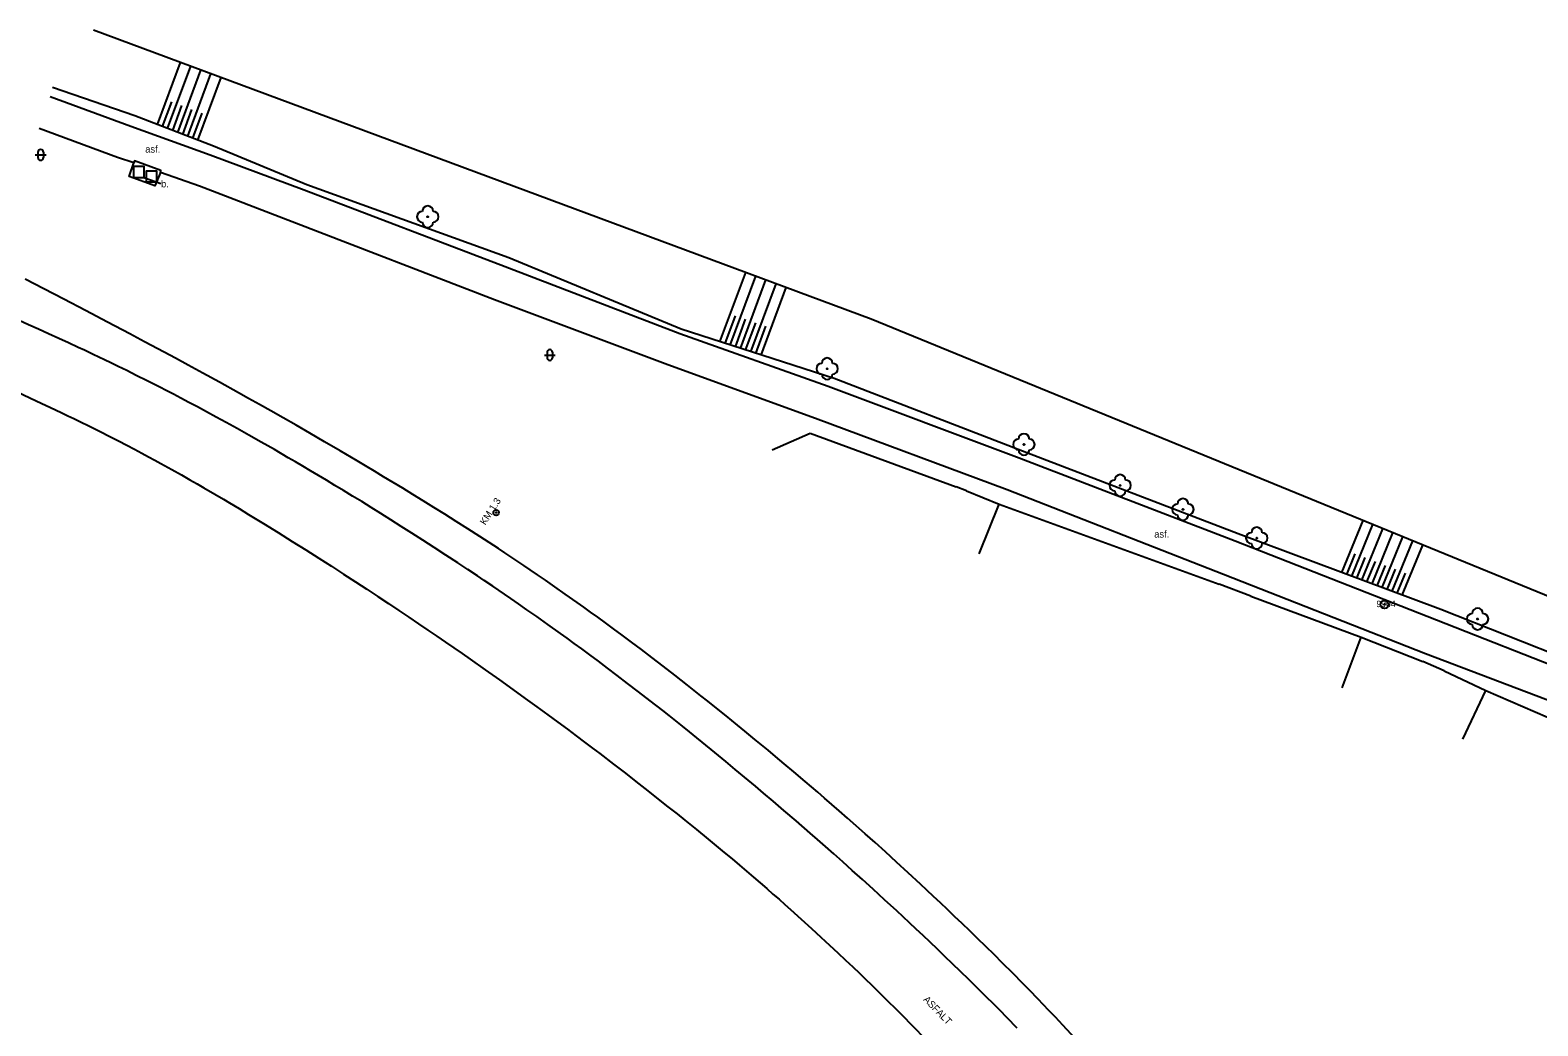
# Model space of a CAD drawing. Extents: x -539244 to -537359, y -1183785 to -1181851.
# Drawn here: x -538699.4 to -538559.5, y -1183314.4 to -1183221.9 of the extents above; entities that cross this region are included whole.
import ezdxf

# ---------------------------------------------------------------- set-up
doc = ezdxf.new("R2010")
doc.units = 0
for name, color, linetype in [('Vrstva 10', 7, 'Continuous'), ('Vrstva 11', 7, 'Continuous'), ('Vrstva 13', 7, 'Continuous'), ('Vrstva 14', 7, 'Continuous'), ('Vrstva 15', 7, 'Continuous'), ('Vrstva 21', 7, 'Continuous'), ('Vrstva 22', 7, 'Continuous'), ('Vrstva 23', 7, 'Continuous'), ('Vrstva 25', 7, 'Continuous'), ('Vrstva 26', 7, 'Continuous'), ('Vrstva 36', 7, 'Continuous'), ('Vrstva 40', 7, 'Continuous'), ('Vrstva 59', 7, 'Continuous'), ('Vrstva 7', 7, 'Continuous'), ('Vrstva 8', 7, 'Continuous')]:
    doc.layers.add(name, color=color, linetype=linetype)

msp = doc.modelspace()

# ---------------------------------------------------------------- linework, layer by layer
at = {"layer": 'Vrstva 10'}
for p, q in [((-538690.11, -1183230.87), (-538697.6, -1183228.13)), ((-538691.35, -1183233.74), (-538698.6, -1183231.06)), ((-538682.73, -1183233.55), (-538690.11, -1183230.87)), ((-538689.82, -1183234.26), (-538691.35, -1183233.74)), ((-538674.02, -1183236.79), (-538682.73, -1183233.55)), ((-538683.72, -1183236.41), (-538687.35, -1183235.14)), ((-538675.11, -1183239.72), (-538683.72, -1183236.41)), ((-538655.34, -1183243.89), (-538674.02, -1183236.79)), ((-538656.33, -1183246.95), (-538675.11, -1183239.72)), ((-538639.13, -1183250.11), (-538655.34, -1183243.89)), ((-538640.26, -1183252.99), (-538656.33, -1183246.95)), ((-538625.35, -1183255), (-538639.13, -1183250.11)), ((-538694.386, -1183251.652), (-538694.98, -1183251.374)), ((-538626.55, -1183257.99), (-538640.26, -1183252.99)), ((-538607.63, -1183261.67), (-538625.35, -1183255)), ((-538695.405, -1183257.977), (-538694.883, -1183258.23)), ((-538608.75, -1183264.6), (-538626.55, -1183257.99)), ((-538587.57, -1183269.37), (-538607.63, -1183261.67)), ((-538686.293, -1183262.721), (-538685.396, -1183263.224)), ((-538588.67, -1183272.45), (-538608.75, -1183264.6)), ((-538677.782, -1183267.738), (-538676.432, -1183268.573)), ((-538662.983, -1183269.278), (-538664.003, -1183268.625)), ((-538568.89, -1183276.7), (-538587.57, -1183269.37)), ((-538569.91, -1183279.82), (-538588.67, -1183272.45)), ((-538668.185, -1183273.837), (-538667.16, -1183274.51)), ((-538552.51, -1183283.13), (-538568.89, -1183276.7)), ((-538659.344, -1183279.803), (-538658.613, -1183280.313)), ((-538646.694, -1183280.519), (-538647.491, -1183279.927)), ((-538553.75, -1183285.98), (-538569.91, -1183279.82)), ((-538638.89, -1183286.556), (-538639.521, -1183286.052)), ((-538630.476, -1183293.509), (-538631.354, -1183292.765)), ((-538622.188, -1183300.773), (-538623.127, -1183299.928)), ((-538626.045, -1183306.113), (-538625.228, -1183306.869)), ((-538614.53, -1183307.91), (-538615.224, -1183307.245))]:
    msp.add_line(p, q, dxfattribs=at)
for points in [[(-538687.35, -1183235.14), (-538687.3, -1183234.96), (-538689.75, -1183234.07), (-538689.82, -1183234.26)], [(-538694.98, -1183251.374), (-538695.874, -1183250.96), (-538696.77, -1183250.55), (-538697.739, -1183250.111), (-538698.679, -1183249.689), (-538699.59, -1183249.283), (-538700.474, -1183248.892), (-538701.33, -1183248.515), (-538702.161, -1183248.153), (-538702.966, -1183247.804)], [(-538685.455, -1183256.095), (-538686.152, -1183255.731), (-538686.807, -1183255.391), (-538687.421, -1183255.075), (-538688.577, -1183254.487), (-538689.59, -1183253.977), (-538690.48, -1183253.535), (-538691.26, -1183253.151), (-538691.944, -1183252.818), (-538692.543, -1183252.528), (-538693.595, -1183252.025), (-538694.386, -1183251.652)], [(-538704.373, -1183253.819), (-538703.459, -1183254.233), (-538701.862, -1183254.961), (-538700.666, -1183255.511), (-538698.872, -1183256.343), (-538697.08, -1183257.18), (-538696.502, -1183257.452), (-538695.944, -1183257.718), (-538695.405, -1183257.977)], [(-538683.924, -1183256.906), (-538684.713, -1183256.486), (-538685.455, -1183256.095)], [(-538694.883, -1183258.23), (-538693.876, -1183258.725), (-538692.936, -1183259.195), (-538692.058, -1183259.64), (-538691.238, -1183260.062), (-538690.471, -1183260.462), (-538689.754, -1183260.839), (-538689.083, -1183261.197), (-538688.456, -1183261.534), (-538687.869, -1183261.852), (-538687.32, -1183262.153), (-538686.293, -1183262.721)], [(-538675.479, -1183261.618), (-538676.777, -1183260.868), (-538677.997, -1183260.171), (-538679.144, -1183259.523), (-538680.222, -1183258.921), (-538681.236, -1183258.362), (-538682.188, -1183257.841), (-538683.083, -1183257.357), (-538683.924, -1183256.906)], [(-538667.79, -1183266.242), (-538668.668, -1183265.699), (-538669.519, -1183265.176), (-538670.345, -1183264.672), (-538671.147, -1183264.186), (-538671.924, -1183263.718), (-538672.679, -1183263.267), (-538673.411, -1183262.832), (-538674.121, -1183262.412), (-538674.81, -1183262.008), (-538675.479, -1183261.618)], [(-538685.396, -1183263.224), (-538684.614, -1183263.668), (-538683.931, -1183264.059), (-538683.334, -1183264.404), (-538682.292, -1183265.013), (-538681.512, -1183265.474), (-538680.928, -1183265.823), (-538680.053, -1183266.349), (-538679.18, -1183266.88), (-538677.782, -1183267.738)], [(-538664.003, -1183268.625), (-538664.993, -1183267.996), (-538665.954, -1183267.389), (-538666.886, -1183266.805), (-538667.79, -1183266.242)], [(-538676.432, -1183268.573), (-538675.129, -1183269.387), (-538673.869, -1183270.179), (-538672.653, -1183270.951), (-538671.478, -1183271.702), (-538670.342, -1183272.433), (-538669.245, -1183273.144), (-538668.185, -1183273.837)], [(-538655.421, -1183274.278), (-538656.492, -1183273.549), (-538657.297, -1183273.005), (-538657.903, -1183272.599), (-538658.815, -1183271.993), (-538659.73, -1183271.39), (-538660.847, -1183270.66), (-538661.931, -1183269.956), (-538662.983, -1183269.278)], [(-538667.16, -1183274.51), (-538666.17, -1183275.166), (-538665.212, -1183275.804), (-538664.287, -1183276.424), (-538663.392, -1183277.027), (-538662.527, -1183277.614), (-538661.691, -1183278.185), (-538660.882, -1183278.739), (-538660.1, -1183279.279), (-538659.344, -1183279.803)], [(-538647.491, -1183279.927), (-538648.24, -1183279.375), (-538648.944, -1183278.859), (-538649.605, -1183278.378), (-538650.227, -1183277.929), (-538651.396, -1183277.091), (-538652.423, -1183276.362), (-538653.325, -1183275.729), (-538654.117, -1183275.177), (-538654.812, -1183274.697), (-538655.421, -1183274.278)], [(-538658.613, -1183280.313), (-538657.199, -1183281.305), (-538655.878, -1183282.242), (-538654.643, -1183283.125), (-538653.489, -1183283.957), (-538652.409, -1183284.742), (-538651.399, -1183285.481)], [(-538639.521, -1183286.052), (-538640.133, -1183285.565), (-538640.727, -1183285.096), (-538641.88, -1183284.192), (-538642.965, -1183283.35), (-538643.985, -1183282.566), (-538644.944, -1183281.835), (-538645.846, -1183281.154), (-538646.694, -1183280.519)], [(-538651.399, -1183285.481), (-538650.455, -1183286.177), (-538649.571, -1183286.833)], [(-538649.571, -1183286.833), (-538648.744, -1183287.45), (-538647.97, -1183288.031), (-538647.246, -1183288.578), (-538646.568, -1183289.092), (-538645.3, -1183290.061), (-538644.193, -1183290.914), (-538643.226, -1183291.664), (-538642.383, -1183292.324), (-538641.646, -1183292.903)], [(-538631.354, -1183292.765), (-538632.124, -1183292.116), (-538632.799, -1183291.55), (-538633.985, -1183290.562), (-538634.877, -1183289.823), (-538636.22, -1183288.719), (-538637.57, -1183287.62), (-538638.24, -1183287.078), (-538638.89, -1183286.556)], [(-538641.646, -1183292.903), (-538640.359, -1183293.922), (-538639.396, -1183294.691), (-538638.675, -1183295.27), (-538637.596, -1183296.142), (-538636.52, -1183297.02), (-538635.75, -1183297.653), (-538635.008, -1183298.268), (-538634.292, -1183298.866)], [(-538623.127, -1183299.928), (-538624.01, -1183299.138), (-538624.839, -1183298.401), (-538625.62, -1183297.712), (-538626.353, -1183297.068), (-538627.042, -1183296.466), (-538628.338, -1183295.342), (-538629.476, -1183294.363), (-538630.476, -1183293.509)], [(-538634.292, -1183298.866), (-538633.601, -1183299.448), (-538632.934, -1183300.014)], [(-538632.934, -1183300.014), (-538632.29, -1183300.564), (-538631.668, -1183301.099), (-538631.068, -1183301.619), (-538630.489, -1183302.124), (-538629.929, -1183302.615), (-538629.389, -1183303.093), (-538628.867, -1183303.556), (-538627.86, -1183304.459), (-538626.921, -1183305.31), (-538626.045, -1183306.113)], [(-538615.224, -1183307.245), (-538615.898, -1183306.603), (-538616.552, -1183305.982), (-538617.187, -1183305.384), (-538617.804, -1183304.805), (-538619.002, -1183303.689), (-538620.129, -1183302.649), (-538621.19, -1183301.679), (-538622.188, -1183300.773)], [(-538625.228, -1183306.869), (-538624.465, -1183307.581), (-538623.753, -1183308.252), (-538623.088, -1183308.884), (-538622.467, -1183309.478), (-538621.887, -1183310.038)], [(-538607.834, -1183314.562), (-538608.751, -1183313.619), (-538609.443, -1183312.915), (-538609.964, -1183312.389), (-538610.75, -1183311.603), (-538611.54, -1183310.82), (-538612.321, -1183310.053), (-538613.079, -1183309.313), (-538613.815, -1183308.599), (-538614.53, -1183307.91)], [(-538621.887, -1183310.038), (-538621.344, -1183310.564), (-538620.837, -1183311.06), (-538619.891, -1183311.993), (-538619.066, -1183312.814), (-538618.348, -1183313.536), (-538617.722, -1183314.171), (-538617.176, -1183314.728), (-538616.7, -1183315.218), (-538615.869, -1183316.078), (-538615.249, -1183316.727)]]:
    msp.add_lwpolyline(points, dxfattribs=at)
at = {"layer": 'Vrstva 11'}
msp.add_lwpolyline([(-538687.35, -1183235.14), (-538687.87, -1183236.39), (-538690.24, -1183235.53), (-538689.82, -1183234.26)], dxfattribs=at)
at = {"layer": 'Vrstva 13'}
for p, q in [((-538698.171, -1183245.934), (-538699.92, -1183245.032)), ((-538680.107, -1183255.597), (-538681.87, -1183254.621)), ((-538670.654, -1183260.994), (-538672.111, -1183260.143)), ((-538653.603, -1183271.634), (-538654.623, -1183270.95)), ((-538629.444, -1183290.029), (-538630.24, -1183289.361)), ((-538628.537, -1183290.794), (-538629.444, -1183290.029)), ((-538620.054, -1183298.22), (-538621.017, -1183297.351)), ((-538612.938, -1183304.86), (-538613.628, -1183304.199))]:
    msp.add_line(p, q, dxfattribs=at)
for points in [[(-538690.193, -1183250.118), (-538692.254, -1183249.026), (-538694.32, -1183247.94), (-538696.307, -1183246.902), (-538698.171, -1183245.934)], [(-538681.87, -1183254.621), (-538683.415, -1183253.772), (-538684.77, -1183253.033), (-538685.957, -1183252.389), (-538686.997, -1183251.827), (-538688.822, -1183250.848), (-538690.193, -1183250.118)], [(-538672.111, -1183260.143), (-538673.48, -1183259.35), (-538674.765, -1183258.611), (-538675.972, -1183257.922), (-538677.106, -1183257.279), (-538678.17, -1183256.68), (-538679.169, -1183256.12), (-538680.107, -1183255.597)], [(-538662.964, -1183265.622), (-538663.923, -1183265.031), (-538664.854, -1183264.462), (-538665.756, -1183263.914), (-538666.632, -1183263.385), (-538667.481, -1183262.875), (-538668.305, -1183262.383), (-538669.104, -1183261.908), (-538670.654, -1183260.994)], [(-538654.623, -1183270.95), (-538655.39, -1183270.44), (-538655.968, -1183270.06), (-538656.837, -1183269.493), (-538657.71, -1183268.93), (-538658.825, -1183268.217), (-538659.907, -1183267.531), (-538660.957, -1183266.871), (-538661.976, -1183266.235), (-538662.964, -1183265.622)], [(-538646.046, -1183276.95), (-538646.76, -1183276.429), (-538647.43, -1183275.944), (-538648.061, -1183275.49), (-538648.653, -1183275.067), (-538649.767, -1183274.278), (-538650.746, -1183273.592), (-538651.605, -1183272.996), (-538652.36, -1183272.478), (-538653.022, -1183272.027), (-538653.603, -1183271.634)], [(-538644.478, -1183278.106), (-538645.286, -1183277.508), (-538646.046, -1183276.95)], [(-538637.182, -1183283.713), (-538638.427, -1183282.732), (-538639.597, -1183281.818), (-538640.697, -1183280.967), (-538641.732, -1183280.174), (-538642.704, -1183279.436), (-538643.619, -1183278.748), (-538644.478, -1183278.106)], [(-538630.24, -1183289.361), (-538630.939, -1183288.779), (-538632.166, -1183287.765), (-538633.09, -1183287.007), (-538633.785, -1183286.441), (-538634.83, -1183285.594), (-538635.88, -1183284.75), (-538636.541, -1183284.222), (-538637.182, -1183283.713)], [(-538621.017, -1183297.351), (-538621.923, -1183296.54), (-538622.775, -1183295.783), (-538623.576, -1183295.075), (-538624.329, -1183294.414), (-538625.037, -1183293.797), (-538625.703, -1183293.219), (-538626.328, -1183292.68), (-538627.504, -1183291.672), (-538628.537, -1183290.794)], [(-538613.628, -1183304.199), (-538614.297, -1183303.561), (-538614.947, -1183302.945), (-538615.579, -1183302.35), (-538616.191, -1183301.775), (-538616.786, -1183301.22), (-538617.942, -1183300.15), (-538619.03, -1183299.151), (-538620.054, -1183298.22)], [(-538605.868, -1183311.887), (-538606.686, -1183311.045), (-538607.302, -1183310.416), (-538608.233, -1183309.476), (-538609.17, -1183308.54), (-538609.968, -1183307.75), (-538610.744, -1183306.989), (-538611.497, -1183306.254), (-538612.228, -1183305.544), (-538612.938, -1183304.86)], [(-538599.261, -1183319.029), (-538599.859, -1183318.356), (-538600.422, -1183317.728), (-538600.952, -1183317.141), (-538601.451, -1183316.592), (-538601.921, -1183316.078), (-538602.806, -1183315.12), (-538603.585, -1183314.285), (-538604.27, -1183313.557), (-538604.873, -1183312.923), (-538605.403, -1183312.37), (-538605.868, -1183311.887)]]:
    msp.add_lwpolyline(points, dxfattribs=at)
at = {"layer": 'Vrstva 14'}
for p, q in [((-538621.36, -1183248.75), (-538693.58, -1183221.93)), ((-538689.72, -1183229.89), (-538697.38, -1183227.26)), ((-538682.44, -1183232.7), (-538689.72, -1183229.89)), ((-538673.76, -1183236.28), (-538682.44, -1183232.7)), ((-538655, -1183243.08), (-538673.76, -1183236.28)), ((-538639.02, -1183249.7), (-538655, -1183243.08)), ((-538624.8, -1183254.28), (-538639.02, -1183249.7)), ((-538530.25, -1183286.08), (-538621.36, -1183248.75)), ((-538607.34, -1183261.01), (-538624.8, -1183254.28)), ((-538587.29, -1183268.7), (-538607.34, -1183261.01)), ((-538568.48, -1183275.71), (-538587.29, -1183268.7)), ((-538552.18, -1183282.16), (-538568.48, -1183275.71))]:
    msp.add_line(p, q, dxfattribs=at)
at = {"layer": 'Vrstva 15'}
for p, q in [((-538687.615, -1183230.703), (-538685.475, -1183224.94)), ((-538686.682, -1183231.063), (-538684.537, -1183225.288)), ((-538685.749, -1183231.423), (-538683.6, -1183225.636)), ((-538684.816, -1183231.783), (-538682.662, -1183225.984)), ((-538683.883, -1183232.143), (-538681.725, -1183226.333)), ((-538687.148, -1183230.883), (-538686.291, -1183228.575)), ((-538686.215, -1183231.243), (-538685.357, -1183228.931)), ((-538685.282, -1183231.603), (-538684.422, -1183229.286)), ((-538684.349, -1183231.963), (-538683.487, -1183229.641)), ((-538635.408, -1183250.864), (-538633.015, -1183244.422)), ((-538634.455, -1183251.17), (-538632.078, -1183244.77)), ((-538633.502, -1183251.477), (-538631.14, -1183245.118)), ((-538632.549, -1183251.784), (-538630.203, -1183245.466)), ((-538631.596, -1183252.091), (-538629.265, -1183245.814)), ((-538634.931, -1183251.017), (-538633.977, -1183248.448)), ((-538633.978, -1183251.324), (-538633.031, -1183248.772)), ((-538633.026, -1183251.631), (-538632.084, -1183249.095)), ((-538632.073, -1183251.938), (-538631.137, -1183249.419)), ((-538577.692, -1183272.277), (-538575.715, -1183267.452)), ((-538576.754, -1183272.626), (-538574.789, -1183267.831)), ((-538575.817, -1183272.976), (-538573.864, -1183268.21)), ((-538574.879, -1183273.325), (-538572.939, -1183268.589)), ((-538573.942, -1183273.675), (-538572.013, -1183268.968)), ((-538573.004, -1183274.024), (-538571.088, -1183269.348)), ((-538577.223, -1183272.452), (-538576.435, -1183270.528)), ((-538572.067, -1183274.373), (-538570.163, -1183269.727)), ((-538576.285, -1183272.801), (-538575.502, -1183270.889)), ((-538575.348, -1183273.151), (-538574.569, -1183271.25)), ((-538574.41, -1183273.5), (-538573.637, -1183271.612)), ((-538573.473, -1183273.849), (-538572.704, -1183271.973)), ((-538572.535, -1183274.199), (-538571.771, -1183272.334))]:
    msp.add_line(p, q, dxfattribs=at)
at = {"layer": 'Vrstva 21'}
for radius in [0.375, 0.05]:
    msp.add_circle((-538573.72, -1183275.24), radius, dxfattribs=at)
at = {"layer": 'Vrstva 22'}
for centre in [(-538662.54, -1183239.25), (-538625.46, -1183253.36), (-538607.19, -1183260.39), (-538598.26, -1183264.19), (-538592.43, -1183266.42), (-538585.58, -1183269.08), (-538565.08, -1183276.59)]:
    msp.add_circle(centre, 0.05, dxfattribs=at)
for centre, start, end in [((-538662.54, -1183238.75), 0, 180), ((-538663.04, -1183239.25), 90, 270), ((-538662.54, -1183239.75), 180, 0), ((-538662.04, -1183239.25), 270, 90), ((-538625.46, -1183252.86), 0, 180), ((-538625.96, -1183253.36), 90, 270), ((-538625.46, -1183253.86), 180, 0), ((-538624.96, -1183253.36), 270, 90), ((-538607.19, -1183259.89), 0, 180), ((-538607.69, -1183260.39), 90, 270), ((-538607.19, -1183260.89), 180, 0), ((-538606.69, -1183260.39), 270, 90), ((-538598.76, -1183264.19), 90, 270), ((-538598.26, -1183263.69), 0, 180), ((-538597.76, -1183264.19), 270, 90), ((-538598.26, -1183264.69), 180, 0), ((-538592.93, -1183266.42), 90, 270), ((-538592.43, -1183265.92), 0, 180), ((-538591.93, -1183266.42), 270, 90), ((-538592.43, -1183266.92), 180, 0), ((-538586.08, -1183269.08), 90, 270), ((-538585.58, -1183268.58), 0, 180), ((-538585.08, -1183269.08), 270, 90), ((-538585.58, -1183269.58), 180, 0), ((-538565.58, -1183276.59), 90, 270), ((-538565.08, -1183276.09), 0, 180), ((-538564.58, -1183276.59), 270, 90), ((-538565.08, -1183277.09), 180, 0)]:
    msp.add_arc(centre, 0.5, start, end, dxfattribs=at)
at = {"layer": 'Vrstva 25'}
for radius in [0.25, 0.0303]:
    msp.add_circle((-538656.19, -1183266.72), radius, dxfattribs=at)
at = {"layer": 'Vrstva 26'}
for points in [[(-538689.859, -1183235.599), (-538688.861, -1183235.599), (-538688.861, -1183234.599), (-538689.859, -1183234.599)], [(-538688.689, -1183236.019), (-538687.691, -1183236.019), (-538687.691, -1183235.019), (-538688.689, -1183235.019)]]:
    msp.add_lwpolyline(points, close=True, dxfattribs=at)
at = {"layer": 'Vrstva 36'}
for p, q in [((-538698.971, -1183233.506), (-538697.971, -1183233.506)), ((-538698.722, -1183233.255), (-538698.722, -1183233.756)), ((-538698.221, -1183233.255), (-538698.221, -1183233.756)), ((-538651.713, -1183252.087), (-538650.713, -1183252.087)), ((-538651.464, -1183251.836), (-538651.464, -1183252.337)), ((-538650.963, -1183251.836), (-538650.963, -1183252.337))]:
    msp.add_line(p, q, dxfattribs=at)
for centre, start, end in [((-538698.471, -1183233.256), 0, 180), ((-538698.471, -1183233.756), 180, 0), ((-538651.213, -1183251.837), 0, 180), ((-538651.213, -1183252.337), 180, 0)]:
    msp.add_arc(centre, 0.25, start, end, dxfattribs=at)
at = {"layer": 'Vrstva 59'}
msp.add_line((-538688.797, -1183235.639), (-538687.309, -1183236.168), dxfattribs=at)
at = {"layer": 'Vrstva 7'}
for p, q in [((-538630.55, -1183260.88), (-538627.05, -1183259.35)), ((-538627.05, -1183259.35), (-538613.48, -1183264.31)), ((-538612.52, -1183264.7), (-538609.49, -1183265.92)), ((-538611.358, -1183270.558), (-538609.49, -1183265.92)), ((-538609.49, -1183265.92), (-538589.07, -1183273.36)), ((-538586.14, -1183274.48), (-538575.9, -1183278.29)), ((-538577.644, -1183282.976), (-538575.9, -1183278.29)), ((-538575.9, -1183278.29), (-538570.16, -1183280.53)), ((-538568.19, -1183281.39), (-538564.3, -1183283.23)), ((-538566.438, -1183287.75), (-538564.3, -1183283.23)), ((-538564.3, -1183283.23), (-538554.45, -1183287.52))]:
    msp.add_line(p, q, dxfattribs=at)
at = {"layer": 'Vrstva 8'}
for p, q in [((-538612.52, -1183264.7), (-538613.48, -1183264.31)), ((-538586.14, -1183274.48), (-538589.07, -1183273.36)), ((-538568.19, -1183281.39), (-538570.16, -1183280.53))]:
    msp.add_line(p, q, dxfattribs=at)

# ---------------------------------------------------------------- texts
at = {"layer": 'Vrstva 23'}
msp.add_text('9904', height=0.6, dxfattribs=at).set_placement((-538574.47, -1183275.49))
at = {"layer": 'Vrstva 40'}
for s, p in [('asf.', (-538688.764, -1183233.298)), ('b.', (-538687.296, -1183236.524)), ('asf.', (-538595.098, -1183269.034))]:
    msp.add_text(s, height=0.65, dxfattribs=at).set_placement(p)
for s, rotation, p in [('KM 1.3', 57.19324, (-538657.199, -1183267.924)), ('ASFALT', 314.24759, (-538616.577, -1183311.966))]:
    msp.add_text(s, height=0.65, rotation=rotation, dxfattribs=at).set_placement(p)

doc.saveas('drawing.dxf')
